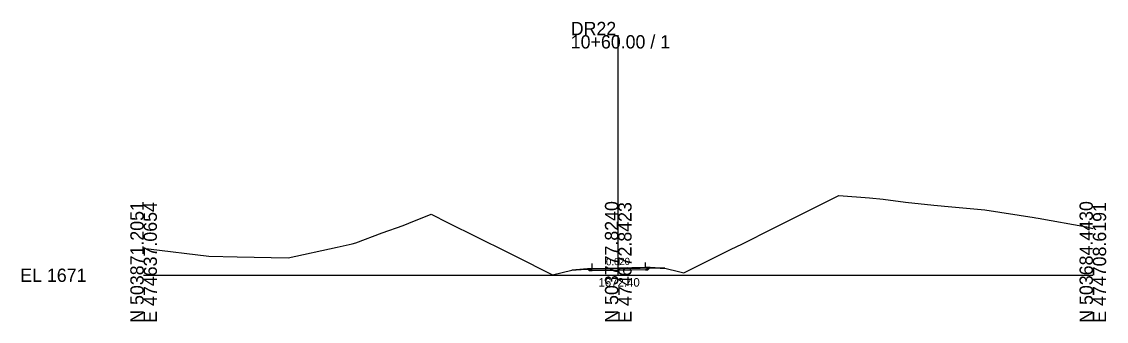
# Model space of a CAD drawing. Extents: x -26 to 1203, y -10 to 9633.
# Drawn here: x -25.7 to 202.8, y 1490.3 to 1553.4 of the extents above; entities that cross this region are included whole.
import ezdxf

# ---------------------------------------------------------------- set-up
doc = ezdxf.new("R2010")
doc.units = 0
for name, color, linetype in [('Exist Cross Section Cell', 7, 'Continuous'), ('Exist XS Center Line Elevation Label', 7, 'Continuous'), ('Exist XS Ground Line', 7, 'Continuous'), ('Prop XS Earthwork Shape', 7, 'Continuous'), ('Prop XS EOT Tick Mark', 7, 'Continuous'), ('Prop XS Finish Grade', 7, 'Continuous'), ('Prop XS Finish Grade Earthwork', 7, 'Continuous'), ('Prop XS Finish Grade Pavement', 7, 'Continuous'), ('Prop XS Pvmt Edge Slope', 7, 'Continuous'), ('Prop XS SE Text', 7, 'Continuous'), ('Prop XS Shoulder Borrow Shape', 7, 'Continuous'), ('Prop XS Subgrade Earthwork', 7, 'Continuous'), ('Scratch_Level_5', 7, 'Continuous')]:
    doc.layers.add(name, color=color, linetype=linetype)

msp = doc.modelspace()

# ---------------------------------------------------------------- linework, layer by layer
at = {"layer": 'Exist Cross Section Cell'}
for p, q in [((100, 1500), (100, 1550.54)), ((0, 1500), (100, 1500)), ((100, 1500), (200, 1500))]:
    msp.add_line(p, q, dxfattribs=at)
at = {"layer": 'Exist XS Ground Line'}
msp.add_lwpolyline([(0, 1505.69), (1.03, 1505.57), (13.77, 1504.04), (19.69, 1503.85), (30.46, 1503.64), (40.79, 1505.94), (43.91, 1506.62), (44.74, 1506.83), (50.26, 1508.93), (54.67, 1510.47), (55.91, 1510.97), (60.57, 1512.87), (64.2, 1511.06), (70.14, 1508.09), (76.65, 1504.84), (80.85, 1502.74), (83.45, 1501.44), (86.18, 1500.08), (90.19, 1501.08), (91.16, 1501.16), (91.56, 1501.19), (92.19, 1501.24), (96.82, 1501.34), (98.27, 1501.36), (100, 1501.4), (102.27, 1501.44), (104.6, 1501.49), (107.81, 1501.56), (108.83, 1501.51), (109.81, 1501.48), (112.98, 1500.69), (113.82, 1500.48), (118.18, 1502.65), (123.69, 1505.4), (126.15, 1506.63), (132.56, 1509.83), (134.4, 1510.75), (135.54, 1511.32), (145.11, 1516.09), (146.5, 1516.79), (152.91, 1516.32), (155.82, 1515.99), (160.52, 1515.42), (166.53, 1514.74), (170.27, 1514.43), (177.24, 1513.8), (187.63, 1512.14), (187.96, 1512.09), (188.47, 1512.01), (198.67, 1510.2), (200, 1509.82)], dxfattribs=at)
at = {"layer": 'Prop XS Earthwork Shape'}
for points in [[(93.59, 1501.27), (96.82, 1501.34), (98.27, 1501.36), (100, 1501.4), (102.27, 1501.44), (104.6, 1501.49), (106.64, 1501.53), (106.25, 1501.15), (105.72, 1501.14), (100, 1501.02), (94.52, 1500.91), (93.96, 1500.9)], [(106.64, 1501.53), (106.75, 1501.64), (109.81, 1501.48), (108.83, 1501.51), (107.81, 1501.56)], [(93.59, 1501.27), (93.49, 1501.37), (90.19, 1501.08), (91.16, 1501.16), (91.56, 1501.19), (92.19, 1501.24)]]:
    msp.add_lwpolyline(points, close=True, dxfattribs=at)
at = {"layer": 'Prop XS EOT Tick Mark'}
for p, q in [((94.52, 1501.45), (94.52, 1502.45)), ((105.72, 1501.68), (105.72, 1502.68))]:
    msp.add_line(p, q, dxfattribs=at)
at = {"layer": 'Prop XS Finish Grade'}
for p, q in [((105.72, 1501.68), (106.75, 1501.64)), ((94.52, 1501.45), (93.49, 1501.37))]:
    msp.add_line(p, q, dxfattribs=at)
at = {"layer": 'Prop XS Finish Grade Earthwork'}
for p, q in [((106.75, 1501.64), (109.81, 1501.48)), ((93.49, 1501.37), (90.19, 1501.08))]:
    msp.add_line(p, q, dxfattribs=at)
at = {"layer": 'Prop XS Finish Grade Pavement'}
for p, q in [((94.52, 1501.45), (100, 1501.56)), ((100, 1501.56), (105.72, 1501.68))]:
    msp.add_line(p, q, dxfattribs=at)
at = {"layer": 'Prop XS Pvmt Edge Slope'}
for p, q in [((105.72, 1501.68), (106.25, 1501.15)), ((94.52, 1501.45), (93.96, 1500.9))]:
    msp.add_line(p, q, dxfattribs=at)
at = {"layer": 'Prop XS Shoulder Borrow Shape'}
for points in [[(106.25, 1501.15), (106.75, 1501.64), (105.72, 1501.68)], [(94.52, 1501.45), (93.96, 1500.9), (93.49, 1501.37)]]:
    msp.add_lwpolyline(points, close=True, dxfattribs=at)
at = {"layer": 'Prop XS Subgrade Earthwork'}
for p, q in [((106.25, 1501.15), (106.75, 1501.64)), ((93.96, 1500.9), (93.49, 1501.37)), ((94.52, 1500.91), (93.96, 1500.9)), ((100, 1501.02), (94.52, 1500.91)), ((105.72, 1501.14), (100, 1501.02)), ((105.72, 1501.14), (106.25, 1501.15))]:
    msp.add_line(p, q, dxfattribs=at)
at = {"layer": 'Scratch_Level_5'}
msp.add_lwpolyline([(0, 1505.69), (1.03, 1505.57), (13.77, 1504.04), (19.69, 1503.85), (30.46, 1503.64), (40.79, 1505.94), (43.91, 1506.62), (44.74, 1506.83), (50.26, 1508.93), (54.67, 1510.47), (55.91, 1510.97), (60.57, 1512.87), (64.2, 1511.06), (70.14, 1508.09), (76.65, 1504.84), (80.85, 1502.74), (83.45, 1501.44), (86.18, 1500.08), (90.19, 1501.08), (91.16, 1501.16), (91.56, 1501.19), (92.19, 1501.24), (96.82, 1501.34), (98.27, 1501.36), (100, 1501.4), (102.27, 1501.44), (104.6, 1501.49), (107.81, 1501.56), (108.83, 1501.51), (109.81, 1501.48), (112.98, 1500.69), (113.82, 1500.48), (118.18, 1502.65), (123.69, 1505.4), (126.15, 1506.63), (132.56, 1509.83), (134.4, 1510.75), (135.54, 1511.32), (145.11, 1516.09), (146.5, 1516.79), (152.91, 1516.32), (155.82, 1515.99), (160.52, 1515.42), (166.53, 1514.74), (170.27, 1514.43), (177.24, 1513.8), (187.63, 1512.14), (187.96, 1512.09), (188.47, 1512.01), (198.67, 1510.2), (200, 1509.82)], dxfattribs=at)

# ---------------------------------------------------------------- texts
at = {"layer": 'Exist Cross Section Cell'}
for s, p in [('DR22', (90, 1550.54)), ('10+60.00 / 1', (90, 1547.74)), ('EL 1671', (-26, 1498.6))]:
    msp.add_text(s, height=2.8, dxfattribs=at).set_placement(p)
for s, p in [('N 503871.2051', (0, 1490)), ('E 474637.0654', (2.8, 1490)), ('N 503777.8240', (100, 1490)), ('E 474672.8423', (102.8, 1490)), ('N 503684.4430', (200, 1490)), ('E 474708.6191', (202.8, 1490))]:
    msp.add_text(s, height=2.8, rotation=90, dxfattribs=at).set_placement(p)
at = {"layer": 'Exist XS Center Line Elevation Label'}
msp.add_text('1672.40', height=1.8, dxfattribs=at).set_placement((95.83, 1497.6))
at = {"layer": 'Prop XS SE Text'}
msp.add_text('0.020', height=1.5, rotation=1.1458, dxfattribs=at).set_placement((97.46, 1502.09))

doc.saveas('drawing.dxf')
